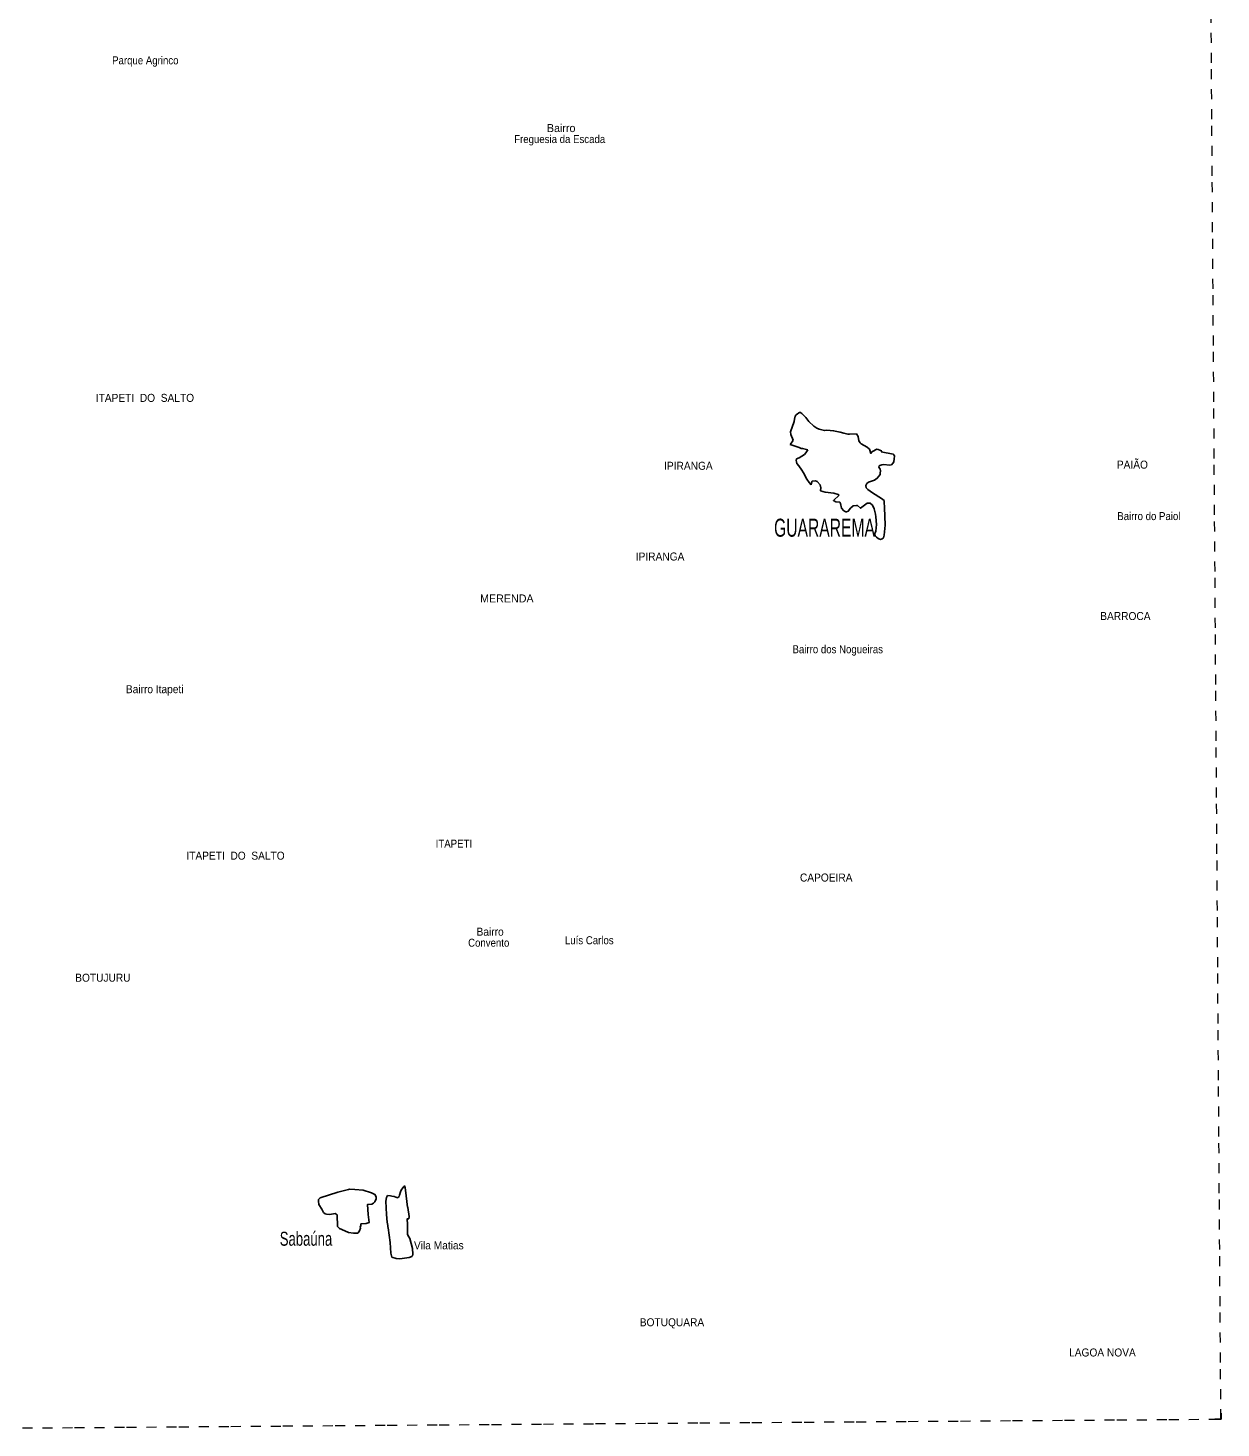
# Model space of a CAD drawing. Extents: x 372.1 to 397.9, y 7400.6 to 7428.4.
# Drawn here: x 385.97 to 397.9, y 7400.68 to 7414.67 of the extents above; entities that cross this region are included whole.
import ezdxf
from ezdxf.enums import TextEntityAlignment as Align

# ---------------------------------------------------------------- set-up
doc = ezdxf.new("R2010")
doc.units = 0
doc.header["$LTSCALE"] = 0.032
doc.linetypes.add('SHORT_DASHED', pattern=[2.7, 1.5, -1.2])
for name, color, linetype, lineweight in [('41', 7, 'Continuous', 25), ('46', 7, 'SHORT_DASHED', 13), ('63', 7, 'Continuous', 25)]:
    doc.layers.add(name, color=color, linetype=linetype, lineweight=lineweight)
doc.layers.add('61', color=7, linetype='Continuous')

msp = doc.modelspace()

# ---------------------------------------------------------------- linework, layer by layer
at = {"layer": '41'}
for points in [[(393.6182, 7410.5497), (393.5948, 7410.6061), (393.5941, 7410.6318), (393.6301, 7410.7358), (393.6317, 7410.7598), (393.638, 7410.7879), (393.6496, 7410.8036), (393.6876, 7410.8288)], [(393.6876, 7410.8288), (393.7067, 7410.8171), (393.7163, 7410.8043), (393.7475, 7410.7755), (393.7768, 7410.7367), (393.8261, 7410.6901), (393.8571, 7410.6677), (393.8779, 7410.6591), (393.9331, 7410.6453), (393.9556, 7410.6491), (394.0229, 7410.6427), (394.0893, 7410.6291), (394.1261, 7410.6179), (394.1525, 7410.6131), (394.1661, 7410.6098), (394.1773, 7410.6082), (394.1821, 7410.6109), (394.2533, 7410.6114)], [(393.5884, 7410.5051), (393.6093, 7410.534), (393.6182, 7410.5497)], [(394.2533, 7410.6114), (394.2693, 7410.5858), (394.2758, 7410.5426), (394.2894, 7410.5234), (394.2998, 7410.5114), (394.359, 7410.4794), (394.383, 7410.4586), (394.3968, 7410.4176), (394.4039, 7410.4308)], [(393.698, 7410.4665), (393.678, 7410.4777), (393.5884, 7410.5051)], [(393.6522, 7410.364), (393.678, 7410.3714), (393.7338, 7410.4072)], [(393.7675, 7410.4539), (393.714, 7410.4675), (393.698, 7410.4665)], [(393.7338, 7410.4072), (393.7472, 7410.4223), (393.7675, 7410.4539)], [(394.4039, 7410.4308), (394.4415, 7410.4527), (394.4571, 7410.458), (394.4697, 7410.4574), (394.5015, 7410.4432), (394.4986, 7410.4337)], [(394.4986, 7410.4337), (394.6194, 7410.4095), (394.6268, 7410.4043), (394.631, 7410.3927), (394.6282, 7410.3601)], [(393.6774, 7410.2926), (393.6575, 7410.3168), (393.6512, 7410.3336), (393.6501, 7410.3472), (393.6522, 7410.364)], [(393.7992, 7410.1041), (393.7803, 7410.1262), (393.7572, 7410.1608), (393.7226, 7410.2238), (393.7068, 7410.2501), (393.6774, 7410.2926)], [(394.6282, 7410.3601), (394.627, 7410.3374), (394.6198, 7410.3211), (394.6177, 7410.3219), (394.6018, 7410.3035), (394.5858, 7410.2995), (394.522, 7410.305), (394.5075, 7410.3037), (394.4871, 7410.2967), (394.4805, 7410.2914), (394.4753, 7410.2792)], [(394.4753, 7410.2792), (394.4894, 7410.2609), (394.4934, 7410.2465), (394.4918, 7410.2321), (394.4883, 7410.2292)], [(393.8103, 7410.1408), (393.8071, 7410.1327), (393.8067, 7410.1317), (393.7992, 7410.1041)], [(393.8922, 7410.0414), (393.8973, 7410.074), (393.8889, 7410.1043), (393.8601, 7410.1358), (393.8421, 7410.144), (393.8103, 7410.1408)], [(394.4883, 7410.2292), (394.4895, 7410.2078), (394.4775, 7410.188), (394.4606, 7410.1694), (394.4318, 7410.1508), (394.373, 7410.1298), (394.355, 7410.1147), (394.3466, 7410.0949), (394.3508, 7410.0734), (394.366, 7410.0566), (394.4116, 7410.023), (394.5041, 7409.9664), (394.5296, 7409.9461)], [(394.0791, 7409.9992), (394.0705, 7410.0065), (394.0275, 7410.0196), (393.9401, 7410.031), (393.8922, 7410.0414)], [(394.2535, 7409.8977), (394.2193, 7409.8936), (394.191, 7409.8696), (394.1703, 7409.8401), (394.1543, 7409.8345), (394.1447, 7409.8345), (394.1271, 7409.8417), (394.1031, 7409.8712), (394.0943, 7409.9157), (394.0859, 7409.9285), (394.045, 7409.9343), (394.0216, 7409.9479), (394.0791, 7409.9992)], [(394.5234, 7409.5739), (394.5099, 7409.5617), (394.4931, 7409.5571), (394.4689, 7409.5662), (394.4531, 7409.5788), (394.4403, 7409.5947), (394.4371, 7409.6091), (394.4372, 7409.6157), (394.4391, 7409.6218), (394.4451, 7409.6411), (394.4523, 7409.705), (394.4467, 7409.7817), (394.4419, 7409.8097), (394.4308, 7409.8632), (394.4116, 7409.9008), (394.39, 7409.9208), (394.3588, 7409.9192), (394.2941, 7409.8695), (394.2616, 7409.895), (394.2535, 7409.8977)], [(394.5339, 7409.8763), (394.5381, 7409.6983), (394.5308, 7409.5991), (394.5234, 7409.5739)], [(394.5296, 7409.9461), (394.5305, 7409.931), (394.5339, 7409.8763)], [(389.5623, 7402.9994), (389.5526, 7402.9804), (389.5469, 7402.9433), (389.5533, 7402.8107), (389.5604, 7402.7324), (389.5676, 7402.6988), (389.5676, 7402.682), (389.5708, 7402.6788), (389.5688, 7402.6753), (389.5892, 7402.531), (389.5964, 7402.4239), (389.6084, 7402.384), (389.6486, 7402.3711), (389.686, 7402.367), (389.7786, 7402.38), (389.8058, 7402.3896), (389.8122, 7402.3984), (389.8169, 7402.4143), (389.8122, 7402.4703), (389.7864, 7402.569), (389.766, 7402.6032), (389.7642, 7402.6143)], [(389.6077, 7402.9924), (389.5927, 7402.9964), (389.5623, 7402.9994)], [(389.665, 7402.9763), (389.6298, 7402.9894), (389.6077, 7402.9924)], [(389.7356, 7403.0949), (389.7262, 7403.0888), (389.7011, 7403.0537), (389.6921, 7403.0366), (389.6851, 7403.0024), (389.679, 7402.9884), (389.665, 7402.9763)], [(389.7754, 7402.7657), (389.7788, 7402.7883), (389.7674, 7402.8802), (389.7643, 7402.8839), (389.7448, 7403.0537), (389.7356, 7403.0949)], [(389.7642, 7402.6143), (389.7642, 7402.7088), (389.76, 7402.765), (389.7754, 7402.7657)]]:
    msp.add_lwpolyline(points, dxfattribs=at)
msp.add_lwpolyline([(389.0602, 7402.8077), (389.0632, 7402.6908), (389.084, 7402.6708), (389.1354, 7402.6459), (389.1752, 7402.6309), (389.224, 7402.6222), (389.2638, 7402.6235), (389.2702, 7402.6272), (389.2831, 7402.6459), (389.292, 7402.6733), (389.2916, 7402.6883), (389.2979, 7402.6952), (389.297, 7402.715), (389.3498, 7402.7206), (389.3796, 7402.7286), (389.3715, 7402.8108), (389.3639, 7402.91), (389.4063, 7402.9148), (389.4243, 7402.9235), (389.4384, 7402.9359), (389.45, 7402.9658), (389.45, 7402.987), (389.4384, 7403.0094), (389.4037, 7403.0256), (389.3207, 7403.0525), (389.2374, 7403.0609), (389.1849, 7403.0635), (389.1733, 7403.0614), (389.0671, 7403.0343), (388.8896, 7402.9772), (388.8735, 7402.9587), (388.8722, 7402.9437), (388.876, 7402.9113), (388.9081, 7402.8628), (388.9223, 7402.8304), (388.9402, 7402.818), (388.9549, 7402.8139), (388.9875, 7402.8115), (389.0419, 7402.8187)], close=True, dxfattribs=at)
at = {"layer": '46'}
for points in [[(397.8958, 7400.7643), (397.8919, 7401.3292), (397.888, 7401.8941), (397.8841, 7402.4589), (397.8801, 7403.0238), (397.8762, 7403.5887), (397.8723, 7404.1536), (397.8683, 7404.7185), (397.8644, 7405.2834), (397.8605, 7405.8483), (397.8566, 7406.4132), (397.8526, 7406.9781), (397.8487, 7407.5429), (397.8448, 7408.1078), (397.8409, 7408.6727), (397.837, 7409.2376), (397.833, 7409.8025), (397.8291, 7410.3674), (397.8252, 7410.9323), (397.8213, 7411.4971), (397.8174, 7412.062), (397.8135, 7412.6269), (397.8095, 7413.1918), (397.8056, 7413.7567), (397.8017, 7414.3216), (397.7978, 7414.8864)], [(385.9132, 7400.676), (386.4342, 7400.68), (386.9552, 7400.684), (387.4762, 7400.688), (387.9972, 7400.692), (388.5182, 7400.696), (389.0392, 7400.7), (389.5602, 7400.7039), (390.0811, 7400.7078), (390.6021, 7400.7117), (391.1231, 7400.7156), (391.6441, 7400.7194), (392.1651, 7400.7233), (392.6861, 7400.7271), (393.207, 7400.7309), (393.728, 7400.7347), (394.249, 7400.7384), (394.77, 7400.7422), (395.291, 7400.7459), (395.8119, 7400.7496), (396.3329, 7400.7533), (396.8539, 7400.757), (397.3749, 7400.7606), (397.8958, 7400.7643)]]:
    msp.add_lwpolyline(points, dxfattribs=at)
at = {"layer": '63'}
msp.add_lwpolyline([(397.8354, 7400.7646), (397.897, 7400.7646), (397.897, 7400.8253)], dxfattribs=at)

# ---------------------------------------------------------------- texts
at = {"layer": '61'}
for s, width, p in [('Parque Agrinco', 0.9, (387.474, 7414.3059)), ('Freguesia da Escada', 0.9, (391.7399, 7413.5188)), ('Bairro do Paiol', 0.9, (397.4915, 7409.7505)), ('Bairro Itapeti', 0.95, (387.5243, 7408.0204)), ('Bairro  ', 0.95, (390.7817, 7405.5965)), ('Convento', 0.9, (390.7817, 7405.4865)), ('Luís Carlos', 0.9, (391.8245, 7405.5112))]:
    msp.add_text(s, height=0.08, dxfattribs=dict(at, width=width)).set_placement(p, align=Align.RIGHT)
msp.add_text(' Bairro          ', height=0.08, dxfattribs=at).set_placement((391.7399, 7413.6288), align=Align.RIGHT)
for s, width, p in [('ITAPETI  DO  SALTO', 0.95, (387.1384, 7410.9322)), ('IPIRANGA', 0.95, (392.5721, 7410.2534)), ('PAIÃO', 0.95, (397.0111, 7410.2651)), ('IPIRANGA', 0.95, (392.2888, 7409.3464)), ('BARROCA', 0.95, (396.9411, 7408.7516)), ('ITAPETI', 0.9, (390.2274, 7406.4767)), ('ITAPETI  DO  SALTO', 0.95, (388.0441, 7406.3563)), ('CAPOEIRA', 0.95, (393.9498, 7406.1379)), ('BOTUJURU', 0.95, (386.718, 7405.1366)), ('BOTUQUARA', 0.95, (392.4078, 7401.6928)), ('LAGOA NOVA', 0.95, (396.7115, 7401.3908))]:
    msp.add_text(s, height=0.08, dxfattribs=dict(at, width=width)).set_placement(p, align=Align.CENTER)
for s, height, width, p in [('GUARAREMA', 0.18, 0.65, (393.4285, 7409.5843)), ('Bairro dos Nogueiras', 0.08, 0.9, (393.6129, 7408.4196)), ('Sabaúna', 0.14, 0.7, (388.4864, 7402.4977)), ('Vila Matias', 0.08, 0.95, (389.8281, 7402.4619))]:
    msp.add_text(s, height=height, dxfattribs=dict(at, width=width)).set_placement(p)
msp.add_text('MERENDA', height=0.08, dxfattribs=at).set_placement((390.7568, 7408.9272), align=Align.CENTER)

doc.saveas('drawing.dxf')
